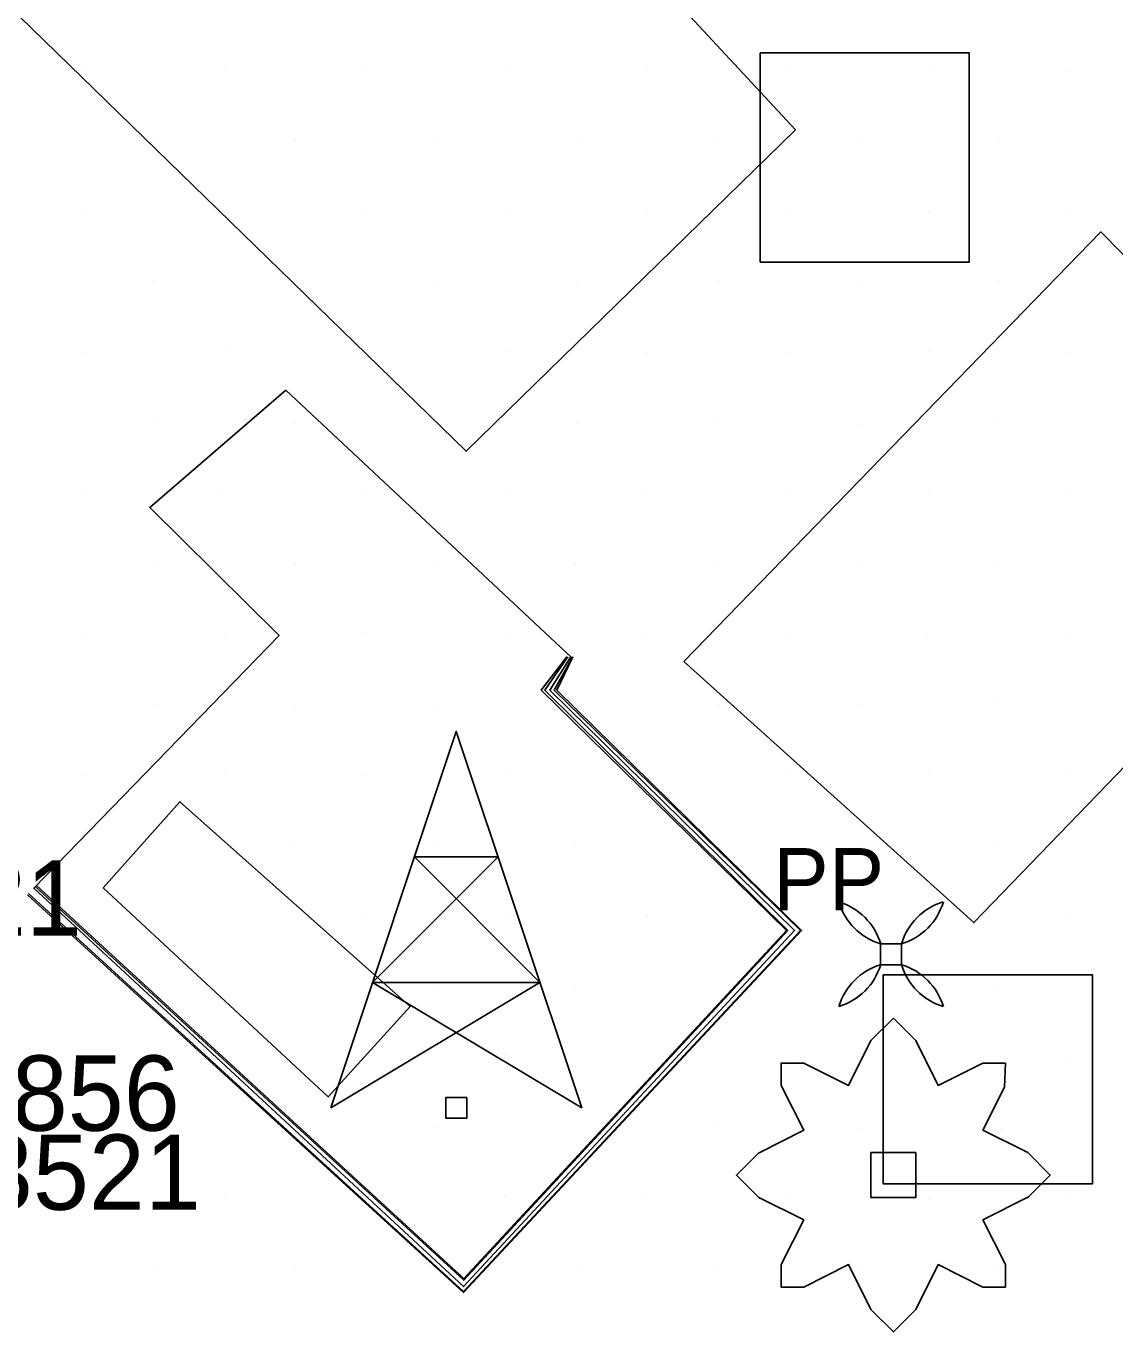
# Model space of a CAD drawing. Extents: x 1602514 to 1609837, y 863887 to 871157.
# Drawn here: x 1605286.1 to 1605395.4, y 866815.4 to 866946.5 of the extents above; entities that cross this region are included whole.
import ezdxf

# ---------------------------------------------------------------- set-up
doc = ezdxf.new("R2010")
doc.units = 0
for name, color, linetype in [('Environmental-New trees', 7, 'Continuous'), ('Photo-Anchor', 7, 'Continuous'), ('Survey-Buildings', 7, 'Continuous'), ('Survey-Fences', 7, 'Continuous'), ('Survey-Misc paved surface', 7, 'Continuous'), ('Survey-Ridge Lines', 7, 'Continuous'), ('Survey-Spot dirt', 7, 'Continuous'), ('Survey-Text-Elevation', 7, 'Continuous'), ('Survey-Walls', 7, 'Continuous'), ('Utility-Pole', 7, 'Continuous')]:
    doc.layers.add(name, color=color, linetype=linetype)

msp = doc.modelspace()

# ---------------------------------------------------------------- linework, layer by layer
at = {"layer": 'Environmental-New trees'}
for points in [[(1605361.94, 866819.88), (1605361.94, 866822.13), (1605364.2, 866826.63), (1605359.69, 866828.88), (1605357.44, 866831.13), (1605359.64, 866833.32), (1605364.2, 866835.63), (1605361.94, 866840.13), (1605361.94, 866842.38), (1605364.2, 866842.38), (1605368.7, 866840.13), (1605370.95, 866844.63), (1605373.2, 866846.88), (1605375.45, 866844.63), (1605377.7, 866840.13), (1605382.2, 866842.38), (1605384.45, 866842.38), (1605384.36, 866839.96), (1605382.2, 866835.63), (1605386.7, 866833.38), (1605388.95, 866831.13), (1605386.76, 866828.94), (1605382.2, 866826.63), (1605384.45, 866822.13), (1605384.45, 866819.88), (1605382.2, 866819.88), (1605377.7, 866822.13), (1605375.45, 866817.63), (1605373.2, 866815.38), (1605370.95, 866817.63), (1605368.7, 866822.13), (1605364.2, 866819.88)], [(1605361.94, 866819.88), (1605361.94, 866822.13), (1605364.2, 866826.63), (1605359.69, 866828.88), (1605357.44, 866831.13), (1605359.64, 866833.32), (1605364.2, 866835.63), (1605361.94, 866840.13), (1605361.94, 866842.38), (1605364.2, 866842.38), (1605368.7, 866840.13), (1605370.95, 866844.63), (1605373.2, 866846.88), (1605375.45, 866844.63), (1605377.7, 866840.13), (1605382.2, 866842.38), (1605384.45, 866842.38), (1605384.36, 866839.96), (1605382.2, 866835.63), (1605386.7, 866833.38), (1605388.95, 866831.13), (1605386.76, 866828.94), (1605382.2, 866826.63), (1605384.45, 866822.13), (1605384.45, 866819.88), (1605382.2, 866819.88), (1605377.7, 866822.13), (1605375.45, 866817.63), (1605373.2, 866815.38), (1605370.95, 866817.63), (1605368.7, 866822.13), (1605364.2, 866819.88)], [(1605370.95, 866833.38), (1605375.45, 866833.38), (1605375.45, 866828.88), (1605370.95, 866828.88)], [(1605370.95, 866833.38), (1605375.45, 866833.38), (1605375.45, 866828.88), (1605370.95, 866828.88)]]:
    msp.add_lwpolyline(points, close=True, dxfattribs=at)
at = {"layer": 'Photo-Anchor'}
msp.add_lwpolyline([(1605371.92, 866854.35), (1605374.02, 866854.35), (1605374.02, 866852.25), (1605371.92, 866852.25)], close=True, dxfattribs=at)
msp.add_lwpolyline([(1605371.92, 866854.35), (1605374.02, 866854.35), (1605374.02, 866852.25), (1605371.92, 866852.25)], close=True, dxfattribs=at)
for centre, radius, start, end in [((1605365.92, 866852.55), 6.27, 16.7236, 73.2821), ((1605373.74, 866860.37), 6.29, 196.8106, 253.1951), ((1605365.92, 866852.55), 6.27, 16.7236, 73.2821), ((1605373.74, 866860.37), 6.29, 196.8106, 253.1951), ((1605380.02, 866852.55), 6.27, 106.7179, 163.2764), ((1605372.2, 866860.37), 6.29, 286.8049, 343.1894), ((1605380.02, 866852.55), 6.27, 106.7179, 163.2764), ((1605372.2, 866860.37), 6.29, 286.8049, 343.1894), ((1605365.92, 866854.06), 6.27, 286.7179, 343.2764), ((1605373.74, 866846.23), 6.29, 106.8049, 163.1894), ((1605365.92, 866854.06), 6.27, 286.7179, 343.2764), ((1605373.74, 866846.23), 6.29, 106.8049, 163.1894), ((1605380.02, 866854.06), 6.27, 196.7236, 253.2821), ((1605372.2, 866846.23), 6.29, 16.8106, 73.1951), ((1605380.02, 866854.06), 6.27, 196.7236, 253.2821), ((1605372.2, 866846.23), 6.29, 16.8106, 73.1951)]:
    msp.add_arc(centre, radius, start, end, dxfattribs=at)
at = {"layer": 'Survey-Buildings'}
msp.add_lwpolyline([(1605293.84, 866859.97), (1605301.55, 866868.61), (1605324.67, 866848.07), (1605316.45, 866838.97)], close=True, dxfattribs=at)
msp.add_lwpolyline([(1605293.84, 866859.97), (1605301.55, 866868.61), (1605324.67, 866848.07), (1605316.45, 866838.97)], close=True, dxfattribs=at)
at = {"layer": 'Survey-Fences'}
msp.add_lwpolyline([(1605276.69, 866955.98), (1605312.32, 866991.05), (1605363.36, 866936.1), (1605330.31, 866903.81)], close=True, dxfattribs=at)
msp.add_lwpolyline([(1605276.69, 866955.98), (1605312.32, 866991.05), (1605363.36, 866936.1), (1605330.31, 866903.81)], close=True, dxfattribs=at)
msp.add_lwpolyline([(1605312.18, 866909.96), (1605340.81, 866883.17), (1605338.71, 866879.82), (1605363.28, 866855.68), (1605330.03, 866819.92), (1605286.86, 866859.93), (1605311.5, 866885.31), (1605298.51, 866898.16), (1605312.18, 866909.96)], dxfattribs=at)
msp.add_lwpolyline([(1605312.18, 866909.96), (1605340.81, 866883.17), (1605338.71, 866879.82), (1605363.28, 866855.68), (1605330.03, 866819.92), (1605286.86, 866859.93), (1605311.5, 866885.31), (1605298.51, 866898.16), (1605312.18, 866909.96)], dxfattribs=at)
at = {"layer": 'Survey-Misc paved surface'}
msp.add_lwpolyline([(1605352.17, 866882.69), (1605394.05, 866925.83), (1605421.42, 866898.04), (1605381.27, 866856.48)], close=True, dxfattribs=at)
msp.add_lwpolyline([(1605352.17, 866882.69), (1605394.05, 866925.83), (1605421.42, 866898.04), (1605381.27, 866856.48)], close=True, dxfattribs=at)
at = {"layer": 'Survey-Ridge Lines'}
for points in [[(1605341.02, 866883.17), (1605339.41, 866879.81), (1605363.98, 866855.68), (1605330.02, 866819.33), (1605286.23, 866859.28)], [(1605341.02, 866883.17), (1605339.41, 866879.81), (1605363.98, 866855.68), (1605330.02, 866819.33), (1605286.23, 866859.28)], [(1605287.13, 866860.21), (1605330.05, 866820.75), (1605362.46, 866855.69), (1605337.84, 866879.83), (1605340.39, 866883.16)], [(1605287.13, 866860.21), (1605330.05, 866820.75), (1605362.46, 866855.69), (1605337.84, 866879.83), (1605340.39, 866883.16)]]:
    msp.add_lwpolyline(points, dxfattribs=at)
at = {"layer": 'Survey-Spot dirt'}
for p, q in [((1605291.87, 866942.11), (1605291.87, 866942.11)), ((1605291.87, 866942.11), (1605291.87, 866942.11)), ((1605306.01, 866942.03), (1605306.01, 866942.03)), ((1605306.01, 866942.03), (1605306.01, 866942.03)), ((1605320.2, 866942.08), (1605320.2, 866942.08)), ((1605320.2, 866942.08), (1605320.2, 866942.08)), ((1605334.34, 866942.08), (1605334.34, 866942.08)), ((1605334.34, 866942.08), (1605334.34, 866942.08)), ((1605348.52, 866942), (1605348.52, 866942)), ((1605348.52, 866942), (1605348.52, 866942)), ((1605362.55, 866942.17), (1605362.55, 866942.17)), ((1605362.55, 866942.17), (1605362.55, 866942.17)), ((1605376.78, 866942.03), (1605376.78, 866942.03)), ((1605376.78, 866942.03), (1605376.78, 866942.03)), ((1605390.89, 866941.96), (1605390.89, 866941.96)), ((1605390.89, 866941.96), (1605390.89, 866941.96)), ((1605299.03, 866935.07), (1605299.03, 866935.07)), ((1605299.03, 866935.07), (1605299.03, 866935.07)), ((1605313.16, 866934.98), (1605313.16, 866934.98)), ((1605313.16, 866934.98), (1605313.16, 866934.98)), ((1605327.14, 866934.91), (1605327.14, 866934.91)), ((1605327.14, 866934.91), (1605327.14, 866934.91)), ((1605341.43, 866934.87), (1605341.43, 866934.87)), ((1605341.43, 866934.87), (1605341.43, 866934.87)), ((1605355.55, 866934.93), (1605355.55, 866934.93)), ((1605355.55, 866934.93), (1605355.55, 866934.93)), ((1605369.78, 866935.02), (1605369.78, 866935.02)), ((1605369.78, 866935.02), (1605369.78, 866935.02)), ((1605383.87, 866934.95), (1605383.87, 866934.95)), ((1605383.87, 866934.95), (1605383.87, 866934.95)), ((1605291.89, 866927.83), (1605291.89, 866927.83)), ((1605291.89, 866927.83), (1605291.89, 866927.83)), ((1605305.96, 866927.95), (1605305.96, 866927.95)), ((1605305.96, 866927.95), (1605305.96, 866927.95)), ((1605320.16, 866927.82), (1605320.16, 866927.82)), ((1605320.16, 866927.82), (1605320.16, 866927.82)), ((1605334.28, 866927.98), (1605334.28, 866927.98)), ((1605334.28, 866927.98), (1605334.28, 866927.98)), ((1605348.53, 866928), (1605348.53, 866928)), ((1605348.53, 866928), (1605348.53, 866928)), ((1605362.56, 866927.83), (1605362.56, 866927.83)), ((1605362.56, 866927.83), (1605362.56, 866927.83)), ((1605376.74, 866927.87), (1605376.74, 866927.87)), ((1605376.74, 866927.87), (1605376.74, 866927.87)), ((1605390.88, 866927.93), (1605390.88, 866927.93)), ((1605390.88, 866927.93), (1605390.88, 866927.93)), ((1605298.87, 866920.99), (1605298.87, 866920.99)), ((1605298.87, 866920.99), (1605298.87, 866920.99)), ((1605313.1, 866920.84), (1605313.1, 866920.84)), ((1605313.1, 866920.84), (1605313.1, 866920.84)), ((1605327.25, 866920.87), (1605327.25, 866920.87)), ((1605327.25, 866920.87), (1605327.25, 866920.87)), ((1605341.34, 866920.84), (1605341.34, 866920.84)), ((1605341.34, 866920.84), (1605341.34, 866920.84)), ((1605355.59, 866920.91), (1605355.59, 866920.91)), ((1605355.59, 866920.91), (1605355.59, 866920.91)), ((1605369.56, 866920.81), (1605369.56, 866920.81)), ((1605369.56, 866920.81), (1605369.56, 866920.81)), ((1605383.73, 866920.91), (1605383.73, 866920.91)), ((1605383.73, 866920.91), (1605383.73, 866920.91)), ((1605291.89, 866913.72), (1605291.89, 866913.72)), ((1605291.89, 866913.72), (1605291.89, 866913.72)), ((1605306.1, 866913.88), (1605306.1, 866913.88)), ((1605306.1, 866913.88), (1605306.1, 866913.88)), ((1605334.35, 866913.83), (1605334.35, 866913.83)), ((1605334.35, 866913.83), (1605334.35, 866913.83)), ((1605348.45, 866913.74), (1605348.45, 866913.74)), ((1605348.45, 866913.74), (1605348.45, 866913.74)), ((1605362.6, 866913.77), (1605362.6, 866913.77)), ((1605362.6, 866913.77), (1605362.6, 866913.77)), ((1605376.81, 866913.81), (1605376.81, 866913.81)), ((1605376.81, 866913.81), (1605376.81, 866913.81)), ((1605390.83, 866913.75), (1605390.83, 866913.75)), ((1605390.83, 866913.75), (1605390.83, 866913.75)), ((1605320.14, 866913.71), (1605320.14, 866913.71)), ((1605320.14, 866913.71), (1605320.14, 866913.71)), ((1605298.85, 866906.69), (1605298.85, 866906.69)), ((1605298.85, 866906.69), (1605298.85, 866906.69)), ((1605313.1, 866906.56), (1605313.1, 866906.56)), ((1605313.1, 866906.56), (1605313.1, 866906.56)), ((1605327.23, 866906.68), (1605327.23, 866906.68)), ((1605327.23, 866906.68), (1605327.23, 866906.68)), ((1605341.38, 866906.62), (1605341.38, 866906.62)), ((1605341.38, 866906.62), (1605341.38, 866906.62)), ((1605355.52, 866906.7), (1605355.52, 866906.7)), ((1605355.52, 866906.7), (1605355.52, 866906.7)), ((1605369.77, 866906.52), (1605369.77, 866906.52)), ((1605369.77, 866906.52), (1605369.77, 866906.52)), ((1605383.76, 866906.8), (1605383.76, 866906.8)), ((1605383.76, 866906.8), (1605383.76, 866906.8)), ((1605291.97, 866899.51), (1605291.97, 866899.51)), ((1605291.97, 866899.51), (1605291.97, 866899.51)), ((1605305.87, 866899.52), (1605305.87, 866899.52)), ((1605305.87, 866899.52), (1605305.87, 866899.52)), ((1605320.07, 866899.62), (1605320.07, 866899.62)), ((1605320.07, 866899.62), (1605320.07, 866899.62)), ((1605334.31, 866899.53), (1605334.31, 866899.53)), ((1605334.31, 866899.53), (1605334.31, 866899.53)), ((1605348.3, 866899.61), (1605348.3, 866899.61)), ((1605348.3, 866899.61), (1605348.3, 866899.61)), ((1605362.64, 866899.64), (1605362.64, 866899.64)), ((1605362.64, 866899.64), (1605362.64, 866899.64)), ((1605376.75, 866899.56), (1605376.75, 866899.56)), ((1605376.75, 866899.56), (1605376.75, 866899.56)), ((1605390.92, 866899.63), (1605390.92, 866899.63)), ((1605390.92, 866899.63), (1605390.92, 866899.63)), ((1605299.03, 866892.54), (1605299.03, 866892.54)), ((1605299.03, 866892.54), (1605299.03, 866892.54)), ((1605313.18, 866892.47), (1605313.18, 866892.47)), ((1605313.18, 866892.47), (1605313.18, 866892.47)), ((1605327.25, 866892.41), (1605327.25, 866892.41)), ((1605327.25, 866892.41), (1605327.25, 866892.41)), ((1605341.32, 866892.45), (1605341.32, 866892.45)), ((1605341.32, 866892.45), (1605341.32, 866892.45)), ((1605355.54, 866892.58), (1605355.54, 866892.58)), ((1605355.54, 866892.58), (1605355.54, 866892.58)), ((1605369.72, 866892.59), (1605369.72, 866892.59)), ((1605369.72, 866892.59), (1605369.72, 866892.59)), ((1605383.8, 866892.54), (1605383.8, 866892.54)), ((1605383.8, 866892.54), (1605383.8, 866892.54)), ((1605291.88, 866885.46), (1605291.88, 866885.46)), ((1605291.88, 866885.46), (1605291.88, 866885.46)), ((1605306.06, 866885.5), (1605306.06, 866885.5)), ((1605306.06, 866885.5), (1605306.06, 866885.5)), ((1605320.18, 866885.64), (1605320.18, 866885.64)), ((1605320.18, 866885.64), (1605320.18, 866885.64)), ((1605334.34, 866885.38), (1605334.34, 866885.38)), ((1605334.34, 866885.38), (1605334.34, 866885.38)), ((1605348.39, 866885.4), (1605348.39, 866885.4)), ((1605348.39, 866885.4), (1605348.39, 866885.4)), ((1605362.42, 866885.54), (1605362.42, 866885.54)), ((1605362.42, 866885.54), (1605362.42, 866885.54)), ((1605376.67, 866885.45), (1605376.67, 866885.45)), ((1605376.67, 866885.45), (1605376.67, 866885.45)), ((1605390.95, 866885.49), (1605390.95, 866885.49)), ((1605390.95, 866885.49), (1605390.95, 866885.49)), ((1605298.97, 866878.39), (1605298.97, 866878.39)), ((1605298.97, 866878.39), (1605298.97, 866878.39)), ((1605355.61, 866878.43), (1605355.61, 866878.43)), ((1605355.61, 866878.43), (1605355.61, 866878.43)), ((1605369.71, 866878.4), (1605369.71, 866878.4)), ((1605369.71, 866878.4), (1605369.71, 866878.4)), ((1605383.67, 866878.59), (1605383.67, 866878.59)), ((1605383.67, 866878.59), (1605383.67, 866878.59)), ((1605313.2, 866878.3), (1605313.2, 866878.3)), ((1605313.2, 866878.3), (1605313.2, 866878.3)), ((1605327.2, 866878.28), (1605327.2, 866878.28)), ((1605327.2, 866878.28), (1605327.2, 866878.28)), ((1605291.77, 866871.21), (1605291.77, 866871.21)), ((1605291.77, 866871.21), (1605291.77, 866871.21)), ((1605305.99, 866871.34), (1605305.99, 866871.34)), ((1605305.99, 866871.34), (1605305.99, 866871.34)), ((1605320.19, 866871.27), (1605320.19, 866871.27)), ((1605320.19, 866871.27), (1605320.19, 866871.27)), ((1605334.25, 866871.36), (1605334.25, 866871.36)), ((1605334.25, 866871.36), (1605334.25, 866871.36)), ((1605362.58, 866871.34), (1605362.58, 866871.34)), ((1605362.58, 866871.34), (1605362.58, 866871.34)), ((1605376.72, 866871.32), (1605376.72, 866871.32)), ((1605376.72, 866871.32), (1605376.72, 866871.32)), ((1605390.88, 866871.33), (1605390.88, 866871.33)), ((1605390.88, 866871.33), (1605390.88, 866871.33)), ((1605313.07, 866864.37), (1605313.07, 866864.37)), ((1605313.07, 866864.37), (1605313.07, 866864.37)), ((1605327.36, 866864.18), (1605327.36, 866864.18)), ((1605327.36, 866864.18), (1605327.36, 866864.18)), ((1605341.3, 866864.23), (1605341.3, 866864.23)), ((1605341.3, 866864.23), (1605341.3, 866864.23)), ((1605369.67, 866864.28), (1605369.67, 866864.28)), ((1605369.67, 866864.28), (1605369.67, 866864.28)), ((1605383.72, 866864.35), (1605383.72, 866864.35)), ((1605383.72, 866864.35), (1605383.72, 866864.35)), ((1605320.19, 866857.17), (1605320.19, 866857.17)), ((1605320.19, 866857.17), (1605320.19, 866857.17)), ((1605334.38, 866857.22), (1605334.38, 866857.22)), ((1605334.38, 866857.22), (1605334.38, 866857.22)), ((1605348.5, 866857.14), (1605348.5, 866857.14)), ((1605348.5, 866857.14), (1605348.5, 866857.14)), ((1605376.61, 866857.09), (1605376.61, 866857.09)), ((1605376.61, 866857.09), (1605376.61, 866857.09)), ((1605390.79, 866857.18), (1605390.79, 866857.18)), ((1605390.79, 866857.18), (1605390.79, 866857.18)), ((1605327.3, 866850.13), (1605327.3, 866850.13)), ((1605327.3, 866850.13), (1605327.3, 866850.13)), ((1605341.32, 866850.16), (1605341.32, 866850.16)), ((1605341.32, 866850.16), (1605341.32, 866850.16)), ((1605369.7, 866849.86), (1605369.7, 866849.86)), ((1605369.7, 866849.86), (1605369.7, 866849.86)), ((1605383.77, 866850.08), (1605383.77, 866850.08)), ((1605383.77, 866850.08), (1605383.77, 866850.08)), ((1605291.87, 866843.15), (1605291.87, 866843.15)), ((1605291.87, 866843.15), (1605291.87, 866843.15)), ((1605320.22, 866843.09), (1605320.22, 866843.09)), ((1605320.22, 866843.09), (1605320.22, 866843.09)), ((1605334.2, 866843.17), (1605334.2, 866843.17)), ((1605334.2, 866843.17), (1605334.2, 866843.17)), ((1605362.64, 866843.08), (1605362.64, 866843.08)), ((1605362.64, 866843.08), (1605362.64, 866843.08)), ((1605390.95, 866842.96), (1605390.95, 866842.96)), ((1605390.95, 866842.96), (1605390.95, 866842.96)), ((1605376.71, 866842.88), (1605376.71, 866842.88)), ((1605376.71, 866842.88), (1605376.71, 866842.88)), ((1605299.21, 866835.84), (1605299.21, 866835.84)), ((1605299.21, 866835.84), (1605299.21, 866835.84)), ((1605327.21, 866835.94), (1605327.21, 866835.94)), ((1605327.21, 866835.94), (1605327.21, 866835.94)), ((1605355.47, 866836), (1605355.47, 866836)), ((1605355.47, 866836), (1605355.47, 866836)), ((1605369.8, 866835.77), (1605369.8, 866835.77)), ((1605369.8, 866835.77), (1605369.8, 866835.77)), ((1605383.94, 866835.85), (1605383.94, 866835.85)), ((1605383.94, 866835.85), (1605383.94, 866835.85)), ((1605291.9, 866828.8), (1605291.9, 866828.8)), ((1605291.9, 866828.8), (1605291.9, 866828.8)), ((1605306.05, 866828.79), (1605306.05, 866828.79)), ((1605306.05, 866828.79), (1605306.05, 866828.79)), ((1605334.19, 866828.93), (1605334.19, 866828.93)), ((1605334.19, 866828.93), (1605334.19, 866828.93)), ((1605348.42, 866828.79), (1605348.42, 866828.79)), ((1605348.42, 866828.79), (1605348.42, 866828.79)), ((1605362.68, 866829.19), (1605362.68, 866829.19)), ((1605362.68, 866829.19), (1605362.68, 866829.19)), ((1605376.73, 866828.69), (1605376.73, 866828.69)), ((1605376.73, 866828.69), (1605376.73, 866828.69)), ((1605390.85, 866829.04), (1605390.85, 866829.04)), ((1605390.85, 866829.04), (1605390.85, 866829.04)), ((1605299.15, 866821.99), (1605299.15, 866821.99)), ((1605299.15, 866821.99), (1605299.15, 866821.99)), ((1605313.13, 866821.91), (1605313.13, 866821.91)), ((1605313.13, 866821.91), (1605313.13, 866821.91)), ((1605341.45, 866821.81), (1605341.45, 866821.81)), ((1605341.45, 866821.81), (1605341.45, 866821.81)), ((1605355.65, 866821.71), (1605355.65, 866821.71)), ((1605355.65, 866821.71), (1605355.65, 866821.71)), ((1605369.58, 866821.87), (1605369.58, 866821.87)), ((1605369.58, 866821.87), (1605369.58, 866821.87)), ((1605383.71, 866821.89), (1605383.71, 866821.89)), ((1605383.71, 866821.89), (1605383.71, 866821.89))]:
    msp.add_line(p, q, dxfattribs=at)
at = {"layer": 'Survey-Walls'}
for points in [[(1605286.33, 866859.39), (1605330.02, 866819.44), (1605363.89, 866855.68), (1605339.12, 866879.81), (1605341.01, 866883.17)], [(1605286.33, 866859.39), (1605330.02, 866819.44), (1605363.89, 866855.68), (1605339.12, 866879.81), (1605341.01, 866883.17)], [(1605287.02, 866860.09), (1605330.05, 866820.57), (1605362.59, 866855.69), (1605338.19, 866879.83), (1605340.5, 866883.17)], [(1605287.02, 866860.09), (1605330.05, 866820.57), (1605362.59, 866855.69), (1605338.19, 866879.83), (1605340.5, 866883.17)]]:
    msp.add_lwpolyline(points, dxfattribs=at)
at = {"layer": 'Utility-Pole'}
msp.add_line((1605329.3, 866858.88), (1605329.3, 866858.88), dxfattribs=at)
msp.add_line((1605329.3, 866858.88), (1605329.3, 866858.88), dxfattribs=at)
for points in [[(1605359.82, 866943.82), (1605380.82, 866943.82), (1605380.82, 866922.81), (1605359.82, 866922.81)], [(1605359.82, 866943.82), (1605380.82, 866943.82), (1605380.82, 866922.81), (1605359.82, 866922.81)], [(1605316.7, 866837.88), (1605329.3, 866875.68), (1605341.9, 866837.88), (1605320.9, 866850.48), (1605337.7, 866850.48), (1605316.7, 866837.88)], [(1605316.7, 866837.88), (1605329.3, 866875.68), (1605341.9, 866837.88), (1605320.9, 866850.48), (1605337.7, 866850.48), (1605316.7, 866837.88)], [(1605372.18, 866851.24), (1605393.19, 866851.24), (1605393.19, 866830.24), (1605372.18, 866830.24)], [(1605372.18, 866851.24), (1605393.19, 866851.24), (1605393.19, 866830.24), (1605372.18, 866830.24)], [(1605330.36, 866838.93), (1605330.36, 866836.83), (1605328.26, 866836.83), (1605328.26, 866838.93), (1605330.36, 866838.93)], [(1605330.36, 866838.93), (1605330.36, 866836.83), (1605328.26, 866836.83), (1605328.26, 866838.93), (1605330.36, 866838.93)]]:
    msp.add_lwpolyline(points, close=True, dxfattribs=at)
msp.add_lwpolyline([(1605320.9, 866850.48), (1605333.5, 866863.08), (1605325.1, 866863.08), (1605337.7, 866850.48)], dxfattribs=at)
msp.add_lwpolyline([(1605320.9, 866850.48), (1605333.5, 866863.08), (1605325.1, 866863.08), (1605337.7, 866850.48)], dxfattribs=at)

# ---------------------------------------------------------------- texts
at = {"layer": 'Survey-Text-Elevation'}
for s, p in [('810.5421', (1605249.55, 866855.17)), ('810.5421', (1605249.55, 866855.17)), ('809.5856', (1605259.36, 866835.58)), ('809.5856', (1605259.36, 866835.58)), ('809.3521', (1605261.48, 866827.64)), ('809.3521', (1605261.48, 866827.64))]:
    msp.add_text(s, height=7.56, dxfattribs=at).set_placement(p)
at = {"layer": 'Utility-Pole'}
msp.add_text('PP', height=6.251, dxfattribs=at).set_placement((1605361.13, 866857.71))
msp.add_text('PP', height=6.251, dxfattribs=at).set_placement((1605361.13, 866857.71))

doc.saveas('drawing.dxf')
